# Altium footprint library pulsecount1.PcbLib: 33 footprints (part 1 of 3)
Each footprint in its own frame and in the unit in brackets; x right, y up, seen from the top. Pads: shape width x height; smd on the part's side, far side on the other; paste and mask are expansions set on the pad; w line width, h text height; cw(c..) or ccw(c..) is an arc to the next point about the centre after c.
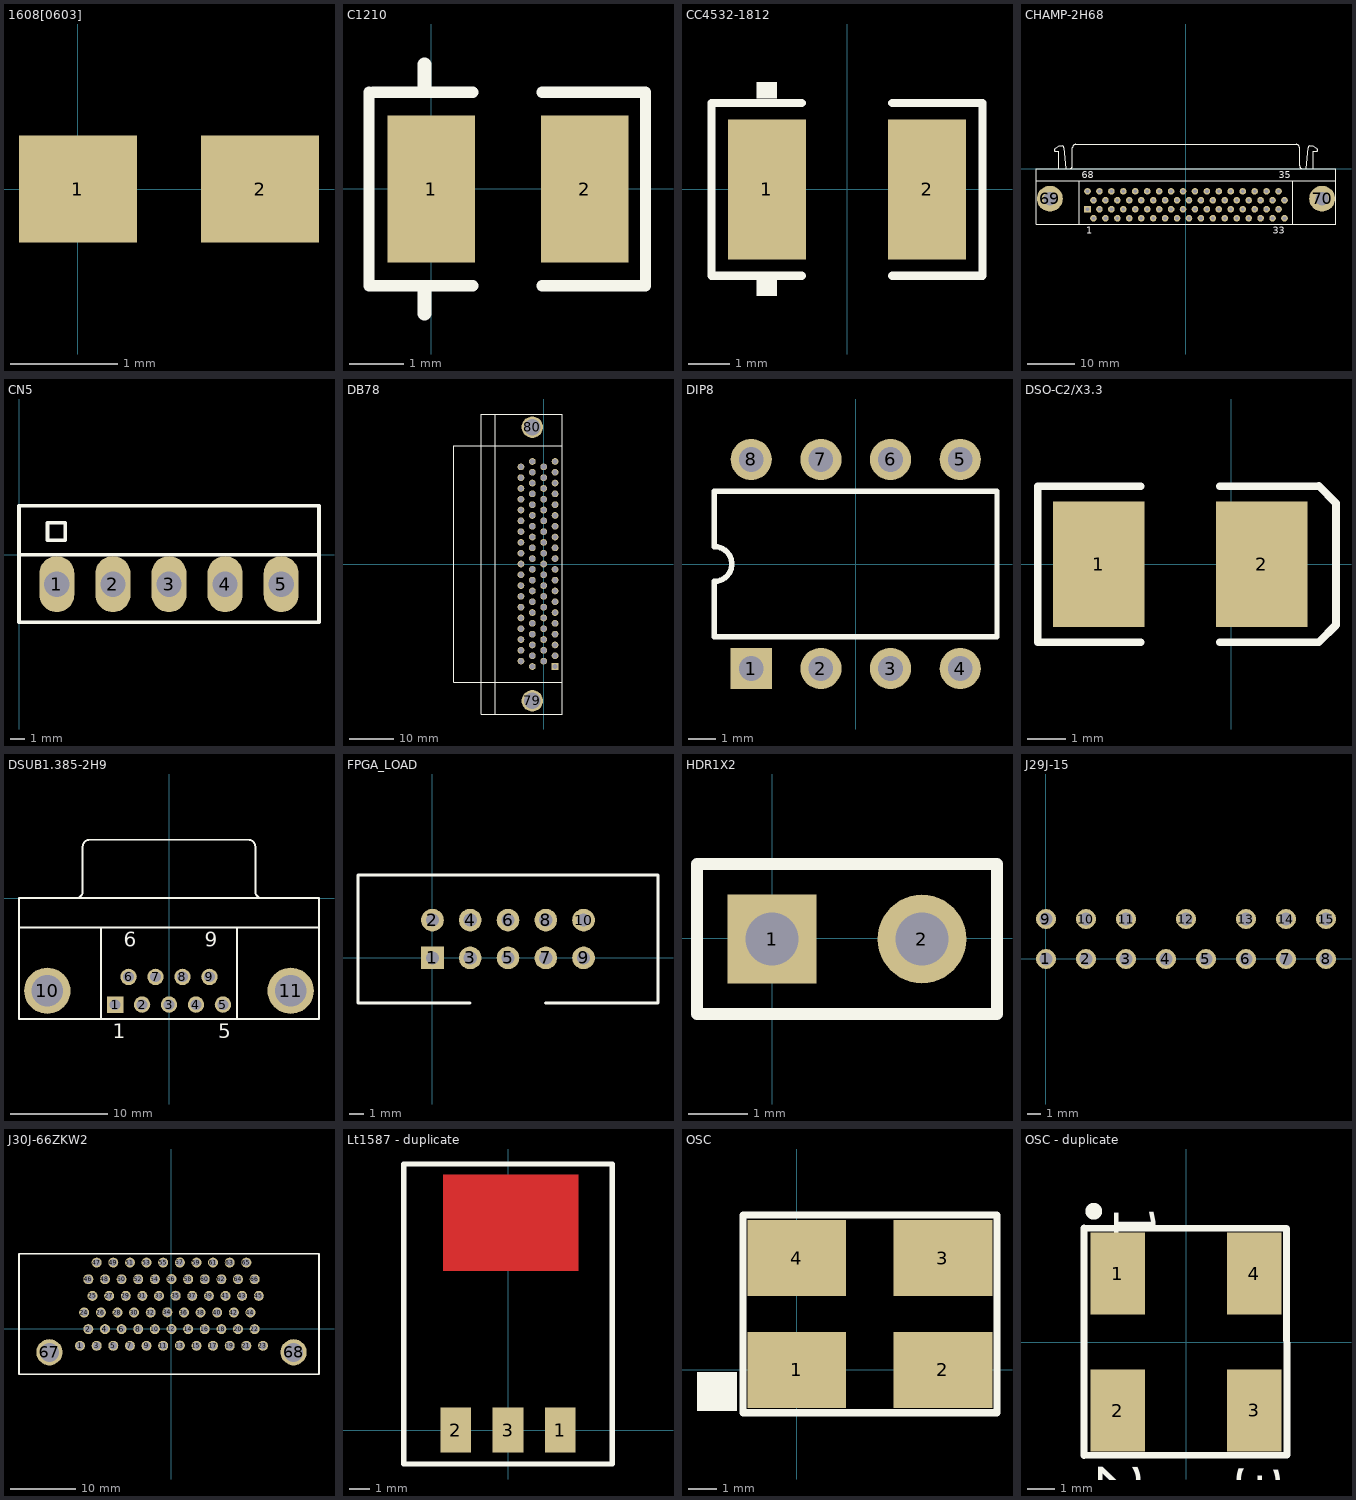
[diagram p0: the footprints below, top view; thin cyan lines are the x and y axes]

## 1608[0603] [mm]
pads (2):
  rect 1.1x1 smd: 1(0,0) 2(1.7,0)

## C1210 [mil]
pads (2):
  rect 63x106 smd: 1(0,0) 2(111,0)
Top Overlay:
  lines w8: -45,70 -45,-70 30,-70 ; -42,70 30,70 ; 80,-70 155,-70 155,70 80,70
  lines w10: -5,-90 -5,-75 ; -5,75 -5,90

## CC4532-1812 [mm]
pads (2):
  rect 1.9x3.4 smd: 1(-1.95,0) 2(1.95,0)
Top Overlay:
  rectangle: -2.2,2.21 -1.7,2.61
  rectangle: -2.2,-2.59 -1.7,-2.19
  lines w0.2: -1.1,-2.1 -3.3,-2.1 -3.3,2.1 -1.1,2.1 ; 1.1,-2.1 3.3,-2.1 3.3,2.1 1.1,2.1

## CHAMP-2H68 [mm]
pads (70):
  rect 1.4x1.4 hole 0.8: 1(-20.955,-8.595)
  round 1.4 hole 0.8: 2(-19.685,-10.5) 3(-18.415,-8.595) 4(-17.145,-10.5) 5(-15.875,-8.595) 6(-14.605,-10.5) 7(-13.335,-8.595) 8(-12.065,-10.5) 9(-10.795,-8.595) 10(-9.525,-10.5) 11(-8.255,-8.595) 12(-6.985,-10.5) 13(-5.715,-8.595) 14(-4.445,-10.5) 15(-3.175,-8.595) 16(-1.905,-10.5) 17(-0.635,-8.595) 18(0.635,-10.5) 19(1.905,-8.595) 20(3.175,-10.5) 21(4.445,-8.595) 22(5.715,-10.5) 23(6.985,-8.595) 24(8.255,-10.5) 25(9.525,-8.595) 26(10.795,-10.5) 27(12.065,-8.595) 28(13.335,-10.5) 29(14.605,-8.595) 30(15.875,-10.5) 31(17.145,-8.595) 32(18.415,-10.5) 33(19.685,-8.595) 34(20.955,-10.5) 35(20.955,-6.69) 36(19.685,-4.785) 37(18.415,-6.69) 38(17.145,-4.785) 39(15.875,-6.69) 40(14.605,-4.785) 41(13.335,-6.69) 42(12.065,-4.785) 43(10.795,-6.69) 44(9.525,-4.785) 45(8.255,-6.69) 46(6.985,-4.785) 47(5.715,-6.69) 48(4.445,-4.785) 49(3.175,-6.69) 50(1.905,-4.785) 51(0.635,-6.69) 52(-0.635,-4.785) 53(-1.905,-6.69) 54(-3.175,-4.785) 55(-4.445,-6.69) 56(-5.715,-4.785) 57(-6.985,-6.69) 58(-8.255,-4.785) 59(-9.525,-6.69) 60(-10.795,-4.785) 61(-12.065,-6.69) 62(-13.335,-4.785) 63(-14.605,-6.69) 64(-15.875,-4.785) 65(-17.145,-6.69) 66(-18.415,-4.785) 67(-19.685,-6.69) 68(-20.955,-4.785)
  round 5.5 hole 2.8: 69(-28.956,-6.35) 70(28.956,-6.35)
Top Overlay:
  lines w0.2: -31.915,-2.5 31.915,-2.5 ; -27.93,4.27 -26.99,4.898 -26.268,4.898 cw(c-26.37,4.5) -25.96,4.5 ; -27.916,4.255 ccw(c-27.69,4.01) -27.94,3.79 -27.06,3.79 -27.06,0 ; -25.96,4.52 -25.59,0 ; -24.85,0.005 ccw(c-24.85,0.7) -24.155,0.7 -24.155,4.5 ; -24.15,4.505 cw(c-23.455,4.505) -23.455,5.2 23.455,5.2 cw(c23.455,4.505) 24.15,4.505 ; -22.715,-11.8 -22.715,-2.58 ; 22.715,-11.8 22.715,-2.5 ; 24.155,4.5 24.155,0.7 ccw(c24.85,0.7) 24.85,0.005 ; 25.59,0 25.96,4.52 ; 25.96,4.5 cw(c26.37,4.5) 26.268,4.898 26.99,4.898 27.93,4.27 ; 27.06,0 27.06,3.79 27.94,3.79 ccw(c27.69,4.01) 27.916,4.255 ; -31.915,-11.8 31.915,-11.8 31.915,0 -31.915,0 -31.915,-11.8
  text "1" at -21.205,-13.775 h1.5
  text "33" at 18.435,-13.775 h1.5
  text "68" at -22.205,-2.025 h1.5
  text "35" at 19.705,-2.025 h1.5

## CN5 [mm]
pads (5):
  oval 2.5x4 hole 1.8: 1(2.7,-2.1) 2(6.7,-2.1) 3(10.7,-2.1) 4(14.7,-2.1) 5(18.7,-2.1)
Top Overlay:
  lines w0.254: 17.9,0 21.4,0 ; 18.034,0 0,0 ; 0,0 0,3.5 17.978,3.5 21.4,3.5 21.4,-4.8 ; 0,0 0,-4.826 18.034,-4.826 21.374,-4.826 ; 21.374,-4.826 21.4,-4.8 ; 21.374,-4.826 21.4,-4.8 ; 2.032,1.016 2.032,2.286 3.302,2.286 3.302,1.016 2.032,1.016

## DB78 [mm]
pads (80):
  rect 1.5x1.5 hole 1.19: 1(2.54,-22.895)
  round 1.5 hole 1.19: 2(0,-21.69) 3(2.54,-20.485) 4(0,-19.28) 5(2.54,-18.075) 6(0,-16.87) 7(2.54,-15.665) 8(0,-14.46) 9(2.54,-13.255) 10(0,-12.05) 11(2.54,-10.845) 12(0,-9.64) 13(2.54,-8.435) 14(0,-7.23) 15(2.54,-6.025) 16(0,-4.82) 17(2.54,-3.615) 18(0,-2.41) 19(2.54,-1.205) 20(0,0) 21(2.54,1.205) 22(0,2.41) 23(2.54,3.615) 24(0,4.82) 25(2.54,6.025) 26(0,7.23) 27(2.54,8.435) 28(0,9.64) 29(2.54,10.845) 30(0,12.05) 31(2.54,13.255) 32(0,14.46) 33(2.54,15.665) 34(0,16.87) 35(2.54,18.075) 36(0,19.28) 37(2.54,20.485) 38(0,21.69) 39(2.54,22.895) 40(-2.54,22.895) 41(-5.08,21.69) 42(-2.54,20.485) 43(-5.08,19.28) 44(-2.54,18.075) 45(-5.08,16.87) 46(-2.54,15.665) 47(-5.08,14.46) 48(-2.54,13.255) 49(-5.08,12.05) 50(-2.54,10.845) 51(-5.08,9.64) 52(-2.54,8.435) 53(-5.08,7.23) 54(-2.54,6.025) 55(-5.08,4.82) 56(-2.54,3.615) 57(-5.08,2.41) 58(-2.54,1.205) 59(-5.08,0) 60(-2.54,-1.205) 61(-5.08,-2.41) 62(-2.54,-3.615) 63(-5.08,-4.82) 64(-2.54,-6.025) 65(-5.08,-7.23) 66(-2.54,-8.435) 67(-5.08,-9.64) 68(-2.54,-10.845) 69(-5.08,-12.05) 70(-2.54,-13.255) 71(-5.08,-14.46) 72(-2.54,-15.665) 73(-5.08,-16.87) 74(-2.54,-18.075) 75(-5.08,-19.28) 76(-2.54,-20.485) 77(-5.08,-21.69) 78(-2.54,-22.895)
  round 4.76 hole 3.75: 79(-2.54,-30.555) 80(-2.54,30.555)
Top Overlay:
  lines w0.254: -10.87,-33.5 -10.87,33.5 ; 4.13,-26.43 -20.07,-26.43 -20.07,26.43 4.13,26.43 ; -13.97,-33.5 4.13,-33.5 4.13,33.5 -13.97,33.5 -13.97,-33.5

## DIP8 [mm]
pads (8):
  rect 1.5x1.5 hole 0.9: 1(-3.81,-3.81)
  round 1.5 hole 0.9: 2(-1.27,-3.81) 3(1.27,-3.81) 4(3.81,-3.81) 5(3.81,3.81) 6(1.27,3.81) 7(-1.27,3.81) 8(-3.81,3.81)
Top Overlay:
  lines w0.2: -5.15,-2.65 -5.15,-0.635 ccw(c-5.15,0) -5.15,0.635 -5.15,2.65 5.15,2.65 5.15,-2.65 -5.15,-2.65

## DSO-C2/X3.3 [mm]
pads (2):
  rect 2.4x3.3 smd: 1(-3.475,0.006) 2(0.808,0.006)
Top Overlay:
  lines w0.2: -2.375,-2.044 -5.075,-2.044 -5.075,2.056 -2.375,2.056 ; -0.292,-2.044 2.308,-2.044 2.758,-1.594 2.758,1.606 2.308,2.061 ; -0.292,2.056 2.308,2.056

## DSUB1.385-2H9 [mm]
pads (11):
  rect 1.69x1.69 hole 1.09: 1(-5.54,-10.92)
  round 1.69 hole 1.09: 2(-2.77,-10.92) 3(0,-10.92) 4(2.77,-10.92) 5(5.54,-10.92) 6(-4.155,-8.08) 7(-1.385,-8.08) 8(1.385,-8.08) 9(4.155,-8.08)
  round 4.76 hole 3.26: 10(-12.495,-9.5) 11(12.495,-9.5)
Top Overlay:
  lines w0.2: -15.4,-3 15.4,-3 ; -9.56,0.005 ccw(c-9.56,0.7) -8.865,0.7 -8.865,5.3 ; -8.86,5.305 cw(c-8.165,5.305) -8.165,6 8.165,6 cw(c8.165,5.305) 8.86,5.305 ; -7,-12.4 -7,-3 ; 7,-12.4 7,-3 ; 8.865,5.3 8.865,0.7 ccw(c9.56,0.7) 9.56,0.005 ; -15.4,-12.4 -15.4,0 15.4,0 15.4,-12.4 -15.4,-12.4
  text "1" at -5.79,-14.375 h1.5
  text "5" at 5.04,-14.375 h1.5
  text "9" at 3.655,-4.975 h1.5
  text "6" at -4.655,-4.975 h1.5

## FPGA_LOAD [mil]
pads (10):
  rect 60x60 hole 35: 1(0,0)
  round 60 hole 35: 2(0,100) 3(100,0) 4(100,100) 5(200,0) 6(200,100) 7(300,0) 8(300,100) 9(400,0) 10(400,100)
Top Overlay:
  lines w8: 99,-119 -197,-119 -197,219 597,219 597,-119 299,-119

## HDR1X2 [mm]
pads (2):
  rect 1.5x1.5 hole 0.9: 1(-0.003,-0.01)
  round 1.5 hole 0.9: 2(2.537,-0.01)
Top Overlay:
  lines w0.2: -1.273,-1.28 3.807,-1.28 3.807,1.26 -1.273,1.26 -1.273,-1.28

## J29J-15 [mm]
pads (15):
  round 1.5 hole 1: 1(0,0) 2(3,0) 3(6,0) 4(9,0) 5(12,0) 6(15,0) 7(18,0) 8(21,0) 9(0,3) 10(3,3) 11(6,3) 12(10.5,3) 13(15,3) 14(18,3) 15(21,3)

## J30J-66ZKW2 [mil]
pads (68):
  round 60 hole 43.31: 1(-550,-101) 2(-500,-1) 3(-450,-101) 4(-400,-1) 5(-350,-101) 6(-300,-1) 7(-250,-101) 8(-200,-1) 9(-150,-101) 10(-100,-1) 11(-50,-101) 12(0,0) 13(50,-100) 14(100,-1) 15(150,-101) 16(200,-1) 17(250,-101) 18(300,-1) 19(350,-101) 20(400,-1) 21(450,-101) 22(500,-1) 23(550,-101) 24(-525,99) 25(-475,199) 26(-425,99) 27(-375,199) 28(-325,99) 29(-275,199) 30(-225,99) 31(-175,199) 32(-125,99) 33(-75,199) 34(-25,100) 35(25,200) 36(75,99) 37(125,199) 38(175,99) 39(225,199) 40(275,99) 41(325,199) 42(375,99) 43(425,199) 44(475,99) 45(525,199) 46(-500,299) 47(-450,399) 48(-400,299) 49(-350,399) 50(-300,299) 51(-250,399) 52(-200,299) 53(-150,399) 54(-100,299) 55(-50,399) 56(0,300) 57(50,400) 58(100,299) 59(150,399) 60(200,299) 61(250,399) 62(300,299) 63(350,399) 64(400,299) 65(450,399) 66(500,299)
  round 157.48 hole 114.17: 67(-734.25,-140.37) 68(734.25,-140.37)
Top Overlay:
  lines w10: -917,-272 887,-272 887,452 -917,452 -917,-272

## Lt1587 - duplicate [mm]
pads (3):
  rect 1.5x2.2 smd: 1(2.54,0) 2(-2.54,0) 3(0,0)
Top Layer:
  rectangle: -3.175,7.747 3.429,12.446
Top Overlay:
  lines w0.254: -5.08,-1.651 5.08,-1.651 5.08,12.954 -5.08,12.954 -5.08,-1.651

## OSC [mm]
pads (4):
  rect 3.5x2.7 smd: 1(0,0) 2(5.182,0) 3(5.182,3.962) 4(0,3.962)
Top Overlay:
  rectangle: -3.531,-1.448 -2.108,-0.076
  lines w0.254: -1.905,-0.514 -1.905,5.486 ; 7.095,-0.514 7.095,5.486 ; -1.905,5.486 -1.905,-1.514 7.095,-1.514 7.095,5.486 ; -1.905,5.486 7.095,5.486

## OSC - duplicate [mm]
pads (4):
  rect 2x3 smd: 1(-2.5,2.502) 2(-2.5,-2.502) 3(2.5,-2.498) 4(2.5,2.502)
Top Overlay:
  circle w0.5: c-3.373,4.788 r0.057
  lines w0.254: -3.723,-4.153 -3.723,4.178 3.668,4.153 3.694,-4.127 -3.723,-4.153
  text "3" at 1.89,-4.458 h1.52
  text "2" at -3.215,-4.407 h1.52
  text "1" at -2.631,4.991 h1.52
